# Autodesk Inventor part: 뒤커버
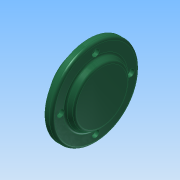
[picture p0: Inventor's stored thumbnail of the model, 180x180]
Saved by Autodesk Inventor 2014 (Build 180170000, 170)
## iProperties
Created: 2015-11
Part Number: 뒤커버
Material: 알루미늄 6061
Document SubType Name: Modeling
Designer: mduedu
Density: 2.71 g/cm^3
Appearance: 매끄러움 - 짙은 바다 녹색
Mass: 309.118 g
Surface Area: 231.217 cm^2
Volume: 114.066 cm^3
Author: mduedu
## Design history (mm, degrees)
sketch "스케치1"
  geometry: C1 r 50 at (0, 0); 1 further point
  constraints: 1 centre point, 1 coincident
  dimensions: "d42" = 100 diameter of C1
extrude "돌출1" new body sketch "스케치1" distance "d3" = 8; taper "d4" = 0 deg
sketch "스케치2"
  geometry: C1 r 35 at (0, 0); 1 further point
  constraints: 1 centre point, 1 coincident
  dimensions: "d5" = 70 diameter of C1
extrude "돌출2" join sketch "스케치2" distance "d6" = 7; taper "d7" = -30 deg
sketch "스케치5" dims "d44" = 80
  geometry: 3 further points
  constraints: 2 vertical alignment, 1 coincident, 2 other
hole "구멍3" sketch "스케치5" at (0, 40) diameter "d45" = 4.5; stored, may be unused: countersink angle "d49" = 90 deg, drill point angle "d51" = 118 deg; dims "d46" = 6, "d47" = 8, "d48" = 4.4, "d50" = 8
sketch "스케치4"
  geometry: C1 r 35 at (0, 0); 1 further point
  constraints: 1 centre point, 1 coincident
  dimensions: "d21" = 70 diameter of C1
extrude "돌출3" join sketch "스케치4" distance "d23" = 12; taper "d24" = 0 deg
hole "구멍2" diameter "d27" = 30; stored, may be unused: countersink angle "d31" = 90 deg, drill point angle "d33" = 0 deg; dims "d25" = 10, "d26" = 10, "d28" = 6, "d29" = 40, "d30" = 12, "d32" = 15
fillet "모깎기3" dims "d36" = 3
fillet "모깎기4" dims "d37" = 3
fillet "모깎기5" dims "d38" = 0.3
chamfer "모따기1" distance "d39" = 1; stored, may be unused: second distance "d40" = 2, angle "d41" = 45 deg
node "솔리드1"
pattern_circular "원형 패턴2" dims angle "d53" = 360 deg
